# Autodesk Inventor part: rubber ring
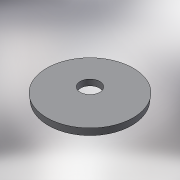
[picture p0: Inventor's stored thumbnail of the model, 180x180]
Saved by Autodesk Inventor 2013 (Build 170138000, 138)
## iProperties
Shininess: 64.0
Length Units: 11269
Angle Units: 11279
Time Units: 11290
Mass Units: 11283
Length Display Precision: 3
Angle Display Precision: 2
Compacted: True
Part Number: rubber ring
Document SubType Name: Modeling
Created: 2004-12
Material: Generic
Designer: =<Author>
Manufacturer: Standard
Standards Organization: Custom
Description: =<Part Number>
Density: 1 g/cm^3
Mass: 18.2369 g
Surface Area: 86.4566 cm^2
Volume: 18.2369 cm^3
Density: 0.0
Volumn: 0.0
Area: 0.0
PropertySet Name: Model Information
Control State: 0
Master: False
Checked Out: False
Checked Out Date: 2008-10-15
Last Check In Date: 2008-10-15
Author: PVitaliy
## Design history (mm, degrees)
sketch "Эскиз1"
  geometry: C1 r 35 at (0, 0); C2 r 8 at (0, 0)
  constraints: 2 centre point, 1 coincident, 1 other
  dimensions: "d0" = 70 diameter of C1; "d1" = 16 diameter of C2
extrude "Выдавливание1" new body sketch "Эскиз1" distance "d2" = 5; taper "d3" = 0 deg
body "Solid1"
